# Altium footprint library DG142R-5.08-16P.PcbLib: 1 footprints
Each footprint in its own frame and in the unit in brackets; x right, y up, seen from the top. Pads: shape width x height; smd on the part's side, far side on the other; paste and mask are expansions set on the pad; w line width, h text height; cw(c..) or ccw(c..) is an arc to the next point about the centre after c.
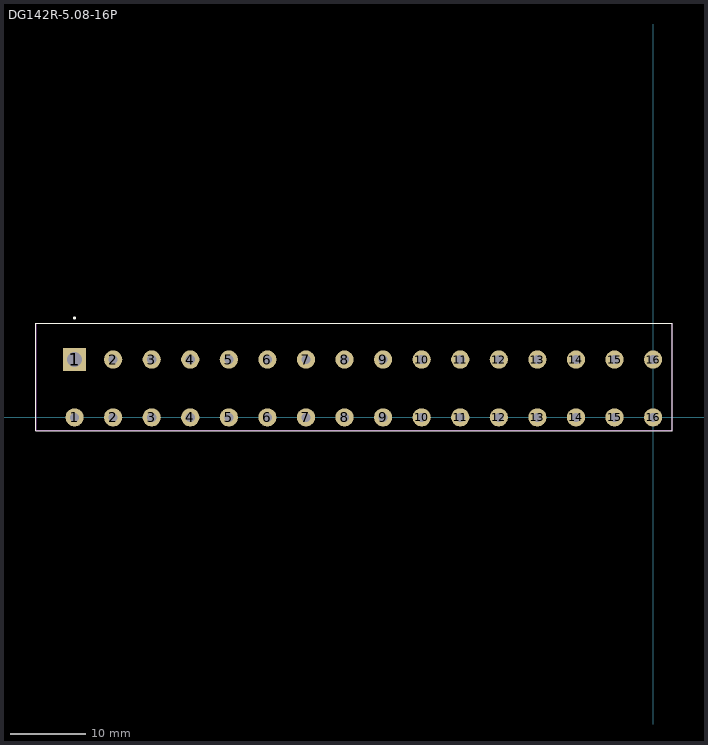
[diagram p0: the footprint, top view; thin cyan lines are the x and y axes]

## DG142R-5.08-16P [mm]
pads (32):
  round 2.4 hole 1.2: 1(-76.2,0) 2(-71.12,0) 2(-71.12,7.62) 3(-66.04,0) 3(-66.04,7.62) 4(-60.96,0) 4(-60.96,7.62) 5(-55.88,0) 5(-55.88,7.62) 6(-50.8,0) 6(-50.8,7.62) 7(-45.72,0) 7(-45.72,7.62) 8(-40.64,0) 8(-40.64,7.62) 9(-35.56,0) 9(-35.56,7.62) 10(-30.48,0) 10(-30.48,7.62) 11(-25.4,0) 11(-25.4,7.62) 12(-20.32,0) 12(-20.32,7.62) 13(-15.24,0) 13(-15.24,7.62) 14(-10.16,0) 14(-10.16,7.62) 15(-5.08,0) 15(-5.08,7.62) 16(0,0) 16(0,7.62)
  rect 3x3 hole 2: 1(-76.2,7.62)
Top Overlay:
  circle w0.2: c-76.225,13.081 r0.1
  lines w0.127: -81.305,-1.753 -81.305,12.37 2.515,12.37 2.515,-1.753 -81.305,-1.753
Mechanical 13:
  lines w0.127: -81.28,-1.702 -81.28,12.421 2.515,12.421 2.515,-1.702 -81.28,-1.702
3D body "DG142R-5.08-16P.stp": height 13.42, standoff -3.48, extent -81.372,-1.716 2.448,12.387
